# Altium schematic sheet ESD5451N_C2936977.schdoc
size 127 x 101 mm
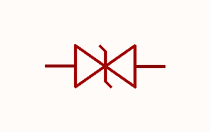
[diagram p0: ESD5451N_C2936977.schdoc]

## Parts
U?  esd5451n_c2936977  [X1-DFN1006-2_L1.0-W0.6-P0.65-BI]  (value not drawn)

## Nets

Not connected (* = marked no-connect by the designer): U? 1 2

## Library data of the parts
U? = esd5451n_c2936977: 极性:双向;反向截止电压(Vrwm):5V;钳位电压:13V;峰值脉冲电流(Ipp):5.5A@8/20us;峰值脉冲功率(Ppp):90W@8/20us;击穿电压:8.4V;; Manufacturer: TECH PUBLIC(台舟); AddInBom: yes; ModelId: e1a2843302f940e8ac07b7d637792d48; ModelTransform: 39.37,23.622,0,0,0,0,0,0,0; Polarity: 双向; Reverse Stand-Off Voltage (Vrwm): 5V; Clamping Voltage: 13V; Voltage - Breakdown: 8.4V; Reverse Leakage Current (Ir): 80nA; Number of Channels: 单路; level of protection: IEC 61000-4-2；IEC 61000-4-5; Junction Capacitance: 12pF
